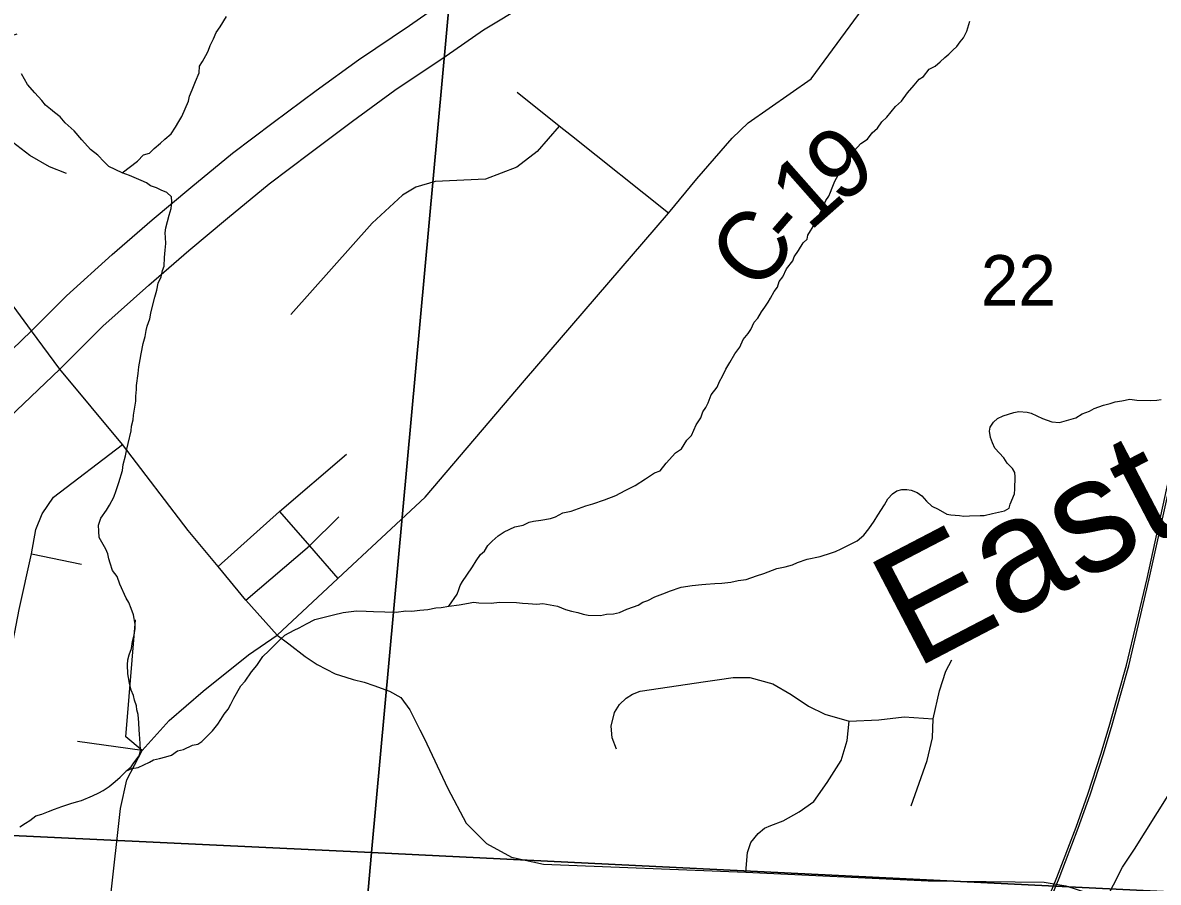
# Model space of a CAD drawing. Extents: x 0 to 34, y 0 to 22.
# Drawn here: x 7.317 to 8.258, y 17.056 to 17.769 of the extents above; entities that cross this region are included whole.
import ezdxf

# ---------------------------------------------------------------- set-up
doc = ezdxf.new("R2010")
doc.units = 0
for name, color, linetype in [('GM_X_County_Road', 7, 'Continuous'), ('GM_X_County_Road_Text', 7, 'Continuous'), ('GM_X_Interstate_Route', 7, 'Continuous'), ('GM_X_Minor_River', 7, 'Continuous'), ('GM_X_Minor_River_Text', 7, 'Continuous'), ('GM_X_Rail_Line', 7, 'Continuous'), ('GM_X_Section', 7, 'Continuous'), ('GM_X_Section_Text', 7, 'Continuous'), ('GM_X_Township_Road', 7, 'Continuous')]:
    doc.layers.add(name, color=color, linetype=linetype)

msp = doc.modelspace()

# ---------------------------------------------------------------- linework, layer by layer
at = {"layer": 'GM_X_County_Road'}
msp.add_lwpolyline([(7.38199, 16.91194), (7.38922, 17.00661), (7.38985, 17.0431), (7.39829, 17.11749), (7.40354, 17.14113), (7.41623, 17.16546), (7.4386, 17.1904), (7.46673, 17.21464), (7.50422, 17.24479), (7.52798, 17.26115), (7.57832, 17.30809), (7.65053, 17.37548), (7.73298, 17.47226), (7.85209, 17.61084), (7.87567, 17.63921), (7.9049, 17.67298), (7.91806, 17.68584), (7.97018, 17.72215), (8.00957, 17.7756), (8.01126, 17.7781)], dxfattribs=at)
at = {"layer": 'GM_X_Interstate_Route'}
for points in [[(7.27583, 17.4668), (7.32445, 17.51346), (7.35347, 17.54247), (7.39147, 17.57652), (7.42453, 17.6053), (7.45661, 17.63212), (7.49115, 17.66057), (7.52471, 17.68591), (7.56024, 17.71255), (7.59528, 17.73805), (7.63755, 17.76651), (7.66848, 17.78822)], [(7.30613, 17.44143), (7.34814, 17.48149), (7.38377, 17.5171), (7.42177, 17.55115), (7.45483, 17.57994), (7.48691, 17.60675), (7.52145, 17.63521), (7.55501, 17.66054), (7.59054, 17.68719), (7.62558, 17.71269), (7.66786, 17.74115), (7.69878, 17.76286), (7.73415, 17.78424)]]:
    msp.add_lwpolyline(points, dxfattribs=at)
at = {"layer": 'GM_X_Minor_River'}
for points in [[(7.3996, 17.6444), (7.41228, 17.65402), (7.4173, 17.65924), (7.42224, 17.66066), (7.4261, 17.66438), (7.43148, 17.66884), (7.43495, 17.67219), (7.44033, 17.67664), (7.44385, 17.68227), (7.44659, 17.68678), (7.44894, 17.69091), (7.4545, 17.70373), (7.45534, 17.70789), (7.45772, 17.71317), (7.4605, 17.71996), (7.46329, 17.72713), (7.46379, 17.73282), (7.46613, 17.73658), (7.46888, 17.74146), (7.47084, 17.74523), (7.47245, 17.74976), (7.47521, 17.75541), (7.47759, 17.76068), (7.4807, 17.76518), (7.48617, 17.77381)], [(8.0875, 17.7461), (8.09096, 17.74907), (8.09368, 17.75282), (8.0964, 17.75618), (8.09916, 17.76183), (8.1016, 17.77015)], [(7.67017, 17.28506), (7.67718, 17.29518), (7.67839, 17.29896), (7.6796, 17.30235), (7.68156, 17.30574), (7.68507, 17.31099), (7.68974, 17.31774), (7.69286, 17.32262), (7.69637, 17.32787), (7.69984, 17.33084), (7.70258, 17.33535), (7.70605, 17.33908), (7.71106, 17.34354), (7.71604, 17.34686), (7.72482, 17.35086), (7.73165, 17.35224), (7.73662, 17.3548), (7.74041, 17.35548), (7.74648, 17.35649), (7.75445, 17.35785), (7.75864, 17.35929), (7.76475, 17.36258), (7.77159, 17.36396), (7.78377, 17.36827), (7.78948, 17.37005), (7.799, 17.37328), (7.80852, 17.37688), (7.81617, 17.38091), (7.82457, 17.3853), (7.833, 17.39083), (7.84066, 17.39561), (7.84523, 17.39742), (7.85028, 17.40378), (7.85801, 17.41237), (7.863, 17.41569), (7.8673, 17.42283), (7.87116, 17.42655), (7.87512, 17.43559), (7.87902, 17.44122), (7.88063, 17.44613), (7.88298, 17.44988), (7.88494, 17.45365), (7.88735, 17.46044), (7.8924, 17.46681), (7.89438, 17.47133), (7.89674, 17.47584), (7.8995, 17.48149), (7.90302, 17.48712), (7.90694, 17.49427), (7.91121, 17.49988), (7.91399, 17.50629), (7.91825, 17.51115), (7.92021, 17.51453), (7.92298, 17.52056), (7.92607, 17.52392), (7.9292, 17.52918), (7.93192, 17.53292), (7.93465, 17.53705), (7.93662, 17.54043), (7.93975, 17.54607), (7.94247, 17.54944), (7.9437, 17.55436), (7.9468, 17.5581), (7.94997, 17.56488), (7.95501, 17.57124), (7.95621, 17.57464), (7.95972, 17.57989), (7.96363, 17.58627), (7.9671, 17.58924), (7.96755, 17.59266), (7.97341, 17.60204), (7.97576, 17.60618), (7.97737, 17.61071), (7.97933, 17.61409), (7.9825, 17.62125), (7.98484, 17.625), (7.98642, 17.62839), (7.98763, 17.63179), (7.99001, 17.63745), (7.99394, 17.64497), (7.9998, 17.65398), (8.0052, 17.65919), (8.00602, 17.6626), (8.01144, 17.66857), (8.01681, 17.67226), (8.02069, 17.67751), (8.02531, 17.68121), (8.02882, 17.68647), (8.03306, 17.69056), (8.04004, 17.69916), (8.04505, 17.70363), (8.0501, 17.71075), (8.05553, 17.7171), (8.05978, 17.72196), (8.06323, 17.72417), (8.06789, 17.73015), (8.07286, 17.73271), (8.07709, 17.73643), (8.08094, 17.73977), (8.0844, 17.74274), (8.0875, 17.7461)], [(7.38005, 17.35232), (7.38205, 17.35798), (7.38673, 17.36473), (7.38908, 17.36887), (7.39262, 17.37564), (7.39462, 17.38092), (7.39702, 17.38772), (7.39987, 17.39755), (7.40035, 17.40248), (7.40239, 17.40967), (7.40364, 17.41535), (7.40448, 17.41989), (7.40697, 17.43049), (7.40742, 17.43428), (7.40867, 17.43958), (7.40912, 17.44338), (7.41087, 17.45513), (7.41096, 17.45931), (7.41144, 17.46463), (7.41151, 17.46805), (7.41285, 17.47791), (7.41334, 17.48361), (7.4146, 17.48967), (7.41545, 17.49421), (7.41714, 17.50292), (7.41877, 17.5086), (7.41962, 17.51352), (7.42046, 17.51731), (7.42247, 17.52335), (7.42332, 17.5279), (7.42455, 17.53282), (7.42661, 17.54114), (7.42825, 17.5472), (7.4295, 17.55287), (7.43187, 17.55815), (7.43312, 17.56345), (7.43432, 17.56685), (7.43484, 17.57406), (7.43534, 17.58014), (7.43584, 17.58583), (7.43556, 17.59078), (7.43526, 17.59459), (7.43573, 17.59877), (7.43859, 17.60936), (7.44021, 17.61465), (7.4407, 17.62034), (7.44041, 17.62453), (7.4367, 17.62803), (7.43183, 17.63003), (7.42808, 17.63201), (7.4232, 17.63364), (7.41985, 17.63599), (7.41535, 17.63798), (7.4056, 17.64199), (7.3996, 17.6444), (7.38874, 17.64957), (7.38466, 17.65346), (7.37948, 17.65889), (7.37353, 17.66358), (7.36613, 17.67172), (7.35986, 17.67907), (7.35243, 17.68569), (7.34837, 17.69072), (7.34353, 17.69425), (7.34018, 17.69698), (7.3361, 17.70048), (7.33315, 17.70435), (7.32723, 17.71056), (7.32132, 17.71753), (7.31621, 17.72638)], [(8.01817, 17.34933), (8.02246, 17.3557), (8.02558, 17.36058), (8.03105, 17.36922), (8.0338, 17.3741), (8.03766, 17.37821), (8.04112, 17.3808), (8.0453, 17.38185), (8.04945, 17.38177), (8.05322, 17.38131), (8.0581, 17.37931), (8.06182, 17.37656), (8.0659, 17.3723), (8.07034, 17.36802), (8.07559, 17.36563), (8.08269, 17.3613), (8.08608, 17.36085), (8.09325, 17.36032), (8.09664, 17.35987), (8.10156, 17.36014), (8.11026, 17.36035), (8.11367, 17.36028), (8.12051, 17.36203), (8.13038, 17.36411), (8.13421, 17.36631), (8.13503, 17.36972), (8.13861, 17.37839), (8.13907, 17.38219), (8.13927, 17.39245), (8.13897, 17.39588), (8.13715, 17.39934), (8.13269, 17.40362), (8.12976, 17.40824), (8.12236, 17.416), (8.12056, 17.4206), (8.11876, 17.42483), (8.11811, 17.43017), (8.11856, 17.43358), (8.12129, 17.43771), (8.12475, 17.44067), (8.12933, 17.44286), (8.13809, 17.44572), (8.14226, 17.4464), (8.14906, 17.44588), (8.15244, 17.44504), (8.16181, 17.44067), (8.16969, 17.43784), (8.1761, 17.43733), (8.18561, 17.44017), (8.18942, 17.44123), (8.19478, 17.44455), (8.20087, 17.4467), (8.20469, 17.4489), (8.21232, 17.45179), (8.21801, 17.45319), (8.2222, 17.45462), (8.22751, 17.45528), (8.23434, 17.45665), (8.24, 17.45578), (8.25095, 17.45555), (8.25663, 17.45581), (8.26005, 17.4565)], [(7.31486, 17.10226), (7.31945, 17.10521), (7.32328, 17.10741), (7.32827, 17.11149), (7.33322, 17.11291), (7.33856, 17.11508), (7.34351, 17.11688), (7.3496, 17.11904), (7.35721, 17.12154), (7.36178, 17.12297), (7.36596, 17.12402), (7.37511, 17.12802), (7.38046, 17.13057), (7.3839, 17.1324), (7.38888, 17.13572), (7.39388, 17.1398), (7.39811, 17.14351), (7.40352, 17.1491), (7.40698, 17.15208), (7.40932, 17.15545), (7.41359, 17.16107), (7.41482, 17.16561), (7.41456, 17.17132), (7.41395, 17.17894), (7.41365, 17.18275), (7.41339, 17.18846), (7.41277, 17.19532), (7.41172, 17.19914), (7.41141, 17.20257), (7.40999, 17.20717), (7.40893, 17.21099), (7.40714, 17.21559), (7.40574, 17.22133), (7.40438, 17.22896), (7.40416, 17.23657), (7.40425, 17.24075), (7.40546, 17.24491), (7.40746, 17.2502), (7.40833, 17.25588), (7.40918, 17.26005), (7.41044, 17.26649), (7.41052, 17.27029), (7.40916, 17.27793), (7.407, 17.2833), (7.40521, 17.28828), (7.40301, 17.29175), (7.39758, 17.30327), (7.39544, 17.30978), (7.39176, 17.3148), (7.38962, 17.32093), (7.38855, 17.32438), (7.38788, 17.32857), (7.38607, 17.33242), (7.3806, 17.34204), (7.38033, 17.34737), (7.38005, 17.35232)], [(7.40275, 17.14836), (7.40771, 17.15054), (7.41302, 17.15157), (7.42218, 17.15594), (7.42562, 17.15778), (7.43056, 17.15881), (7.43588, 17.16022), (7.44044, 17.16165), (7.44544, 17.16535), (7.45037, 17.16639), (7.45801, 17.17003), (7.46218, 17.17071), (7.46563, 17.17292), (7.47103, 17.17851), (7.4745, 17.18186), (7.47878, 17.18748), (7.4815, 17.19123), (7.48424, 17.19573), (7.48734, 17.19985), (7.4897, 17.20399), (7.49207, 17.20888), (7.49794, 17.21903), (7.50143, 17.22314), (7.50687, 17.23064), (7.51114, 17.23587), (7.51621, 17.24337), (7.52122, 17.24821), (7.53048, 17.25753), (7.53434, 17.26125), (7.54198, 17.26528), (7.54618, 17.26709), (7.5523, 17.27039), (7.55918, 17.27405), (7.56905, 17.27651), (7.57475, 17.27791), (7.58274, 17.28003), (7.59373, 17.28132), (7.60166, 17.28115), (7.6077, 17.28065), (7.6266, 17.28025), (7.63456, 17.28123), (7.63947, 17.28113), (7.64629, 17.28175), (7.65273, 17.28237), (7.65956, 17.28375), (7.66373, 17.28405), (7.67017, 17.28506), (7.67889, 17.28639), (7.68648, 17.28776), (7.69066, 17.28843), (7.69518, 17.28796), (7.70539, 17.28775), (7.71221, 17.28837), (7.72619, 17.28807), (7.73109, 17.28759), (7.73601, 17.28749), (7.74318, 17.28696), (7.7481, 17.28724), (7.75413, 17.28635), (7.76015, 17.28509), (7.7669, 17.28228), (7.77179, 17.28104), (7.77706, 17.27979), (7.78157, 17.27856), (7.78571, 17.27771), (7.79592, 17.2775), (7.80085, 17.27854), (7.80653, 17.2788), (7.81146, 17.27984), (7.81757, 17.28275), (7.82328, 17.28454), (7.82709, 17.28598), (7.83092, 17.28856), (7.83511, 17.28999), (7.84084, 17.29292), (7.8496, 17.29616), (7.85303, 17.29761), (7.86255, 17.30083), (7.87165, 17.30217), (7.87961, 17.30314), (7.88302, 17.30345), (7.89059, 17.30406), (7.89627, 17.30432), (7.90384, 17.30492), (7.90992, 17.30631), (7.91637, 17.30732), (7.92512, 17.31018), (7.93122, 17.31234), (7.94188, 17.3163), (7.94872, 17.31768), (7.9548, 17.31946), (7.959, 17.32127), (7.96699, 17.32415), (7.97762, 17.32621), (7.98714, 17.32943), (7.99057, 17.3305), (7.99515, 17.33269), (8.00011, 17.33525), (8.00851, 17.33926), (8.0139, 17.34409), (8.01817, 17.34933)]]:
    msp.add_lwpolyline(points, dxfattribs=at)
at = {"layer": 'GM_X_Rail_Line'}
for points in [[(8.1502, 17.00281), (8.1738, 17.06031), (8.1897, 17.10192), (8.19949, 17.12936), (8.2105, 17.16327), (8.21767, 17.18739), (8.22466, 17.21204), (8.23148, 17.23616), (8.24844, 17.30818), (8.26661, 17.39033), (8.27885, 17.45378), (8.28077, 17.46252), (8.28759, 17.48717), (8.32412, 17.65025), (8.34685, 17.75234), (8.43677, 18.15919)], [(8.15196, 17.00203), (8.17559, 17.05961), (8.19151, 17.10125), (8.20132, 17.12874), (8.21234, 17.1627), (8.21952, 17.18686), (8.22652, 17.21152), (8.23334, 17.23568), (8.25031, 17.30775), (8.2685, 17.38994), (8.28074, 17.4534), (8.28264, 17.46206), (8.28946, 17.4867), (8.326, 17.64984), (8.34873, 17.75192), (8.43874, 18.15919)]]:
    msp.add_lwpolyline(points, dxfattribs=at)
at = {"layer": 'GM_X_Section'}
for points in [[(7.7014, 18.12246), (7.60628, 17.08098), (6.58502, 17.12945), (6.66917, 18.13633)], [(7.7014, 18.12246), (8.69337, 18.03333), (8.60403, 17.03188), (7.60628, 17.08098)], [(8.60403, 17.03188), (8.50373, 16.01286), (7.51567, 16.05493), (7.60628, 17.08098)]]:
    msp.add_lwpolyline(points, close=True, dxfattribs=at)
msp.add_lwpolyline([(6.52248, 16.41448), (6.58502, 17.12945), (7.60628, 17.08098), (7.51567, 16.05493), (7.17775, 16.07236)], dxfattribs=at)
at = {"layer": 'GM_X_Township_Road'}
for p, q in [((7.32447, 17.32863), (7.36599, 17.32005)), ((7.41623, 17.16546), (7.36258, 17.17287))]:
    msp.add_line(p, q, dxfattribs=at)
for points in [[(7.35353, 17.64376), (7.33941, 17.64916), (7.32324, 17.6587), (7.30884, 17.66971), (7.29834, 17.69854), (7.28347, 17.75043), (7.31281, 17.7594)], [(7.85209, 17.61084), (7.77179, 17.67487), (7.76153, 17.68293), (7.72693, 17.7108)], [(7.76153, 17.68293), (7.74331, 17.6619), (7.72649, 17.64893), (7.70057, 17.63912), (7.65888, 17.63702), (7.64276, 17.63246), (7.6319, 17.6258), (7.60667, 17.60268), (7.53941, 17.52698)], [(7.52798, 17.26115), (7.50199, 17.29003), (7.47905, 17.31803), (7.45427, 17.34782), (7.40006, 17.41905), (7.34814, 17.48149), (7.32445, 17.51346), (7.29379, 17.55486), (7.24301, 17.61157)], [(7.30556, 17.13695), (7.29574, 17.14887), (7.29294, 17.16008), (7.30135, 17.21475), (7.31186, 17.26941), (7.31431, 17.28238), (7.32447, 17.32863), (7.32815, 17.34878), (7.33341, 17.36158), (7.34286, 17.37559), (7.40006, 17.41905)], [(7.47905, 17.31803), (7.52999, 17.36362), (7.58552, 17.41121)], [(7.52999, 17.36362), (7.5547, 17.33523), (7.57832, 17.30809)], [(7.50199, 17.29003), (7.5547, 17.33523), (7.57911, 17.35924)], [(8.17563, 16.7928), (8.18121, 16.81299), (8.19299, 16.86147), (8.21671, 16.97503), (8.22539, 17.01932), (8.22497, 17.02533), (8.22068, 17.03359), (8.21328, 17.03949), (8.22818, 17.06877), (8.23816, 17.08389), (8.30272, 17.18675), (8.31249, 17.20648), (8.32992, 17.24177), (8.34051, 17.27604), (8.35225, 17.3455)], [(7.41623, 17.16546), (7.40276, 17.17688), (7.41063, 17.27388)], [(7.52798, 17.26115), (7.53771, 17.25396), (7.55125, 17.24354), (7.56121, 17.23675), (7.57598, 17.22915), (7.58489, 17.22622), (7.59089, 17.22432), (7.59995, 17.22212), (7.60799, 17.2195), (7.62101, 17.21482), (7.63051, 17.20955), (7.63796, 17.19932), (7.64619, 17.18276)], [(8.053, 17.11955), (8.06632, 17.15714), (8.07084, 17.17594), (8.07131, 17.19176), (8.07655, 17.21496), (8.08178, 17.23138), (8.08678, 17.24066)], [(7.80898, 17.16666), (7.80541, 17.17594), (7.8047, 17.18569), (7.80732, 17.19711), (7.8116, 17.20354), (7.81707, 17.20878), (7.82231, 17.21234), (7.82861, 17.21461), (7.88275, 17.2227), (7.8925, 17.22424), (7.90559, 17.22591), (7.91957, 17.22596), (7.93855, 17.22068), (7.95377, 17.21187), (7.96819, 17.20236), (7.98161, 17.19569), (8.00171, 17.18974), (8.02634, 17.19093), (8.04728, 17.19355), (8.07131, 17.19176)], [(7.9163, 17.06484), (7.91754, 17.08102), (7.92025, 17.08939), (7.92653, 17.09671), (7.93175, 17.1011), (7.93695, 17.10329), (7.94723, 17.10737), (7.9604, 17.11469), (7.97237, 17.12326), (7.98361, 17.13915), (7.99511, 17.15734), (8.00017, 17.1738), (8.00171, 17.18974)], [(7.64619, 17.18276), (7.64966, 17.17578), (7.66939, 17.13397), (7.6846, 17.10518), (7.70141, 17.08851), (7.72215, 17.07701), (7.74848, 17.07126), (7.9163, 17.06484), (8.06731, 17.05763), (8.16319, 17.05654), (8.1812, 17.05332), (8.2017, 17.04688), (8.21328, 17.03949)]]:
    msp.add_lwpolyline(points, dxfattribs=at)

# ---------------------------------------------------------------- texts
at = {"layer": 'GM_X_County_Road_Text'}
for s, rotation, p in [('9', 36.86798, (7.99377, 17.61715)), ('1', 41.44431, (7.96867, 17.59492)), ('C', 49.88296, (7.92526, 17.54358)), ('-', 49.18472, (7.95498, 17.57886))]:
    msp.add_text(s, height=0.05682, rotation=rotation, dxfattribs=at).set_placement(p)
at = {"layer": 'GM_X_Minor_River_Text'}
msp.add_text('East', height=0.094692, rotation=27.53796, dxfattribs=at).set_placement((8.05621, 17.23281))
at = {"layer": 'GM_X_Section_Text'}
msp.add_text('22', height=0.041856, rotation=0.00001, dxfattribs=at).set_placement((8.11078, 17.53428))

doc.saveas('drawing.dxf')
